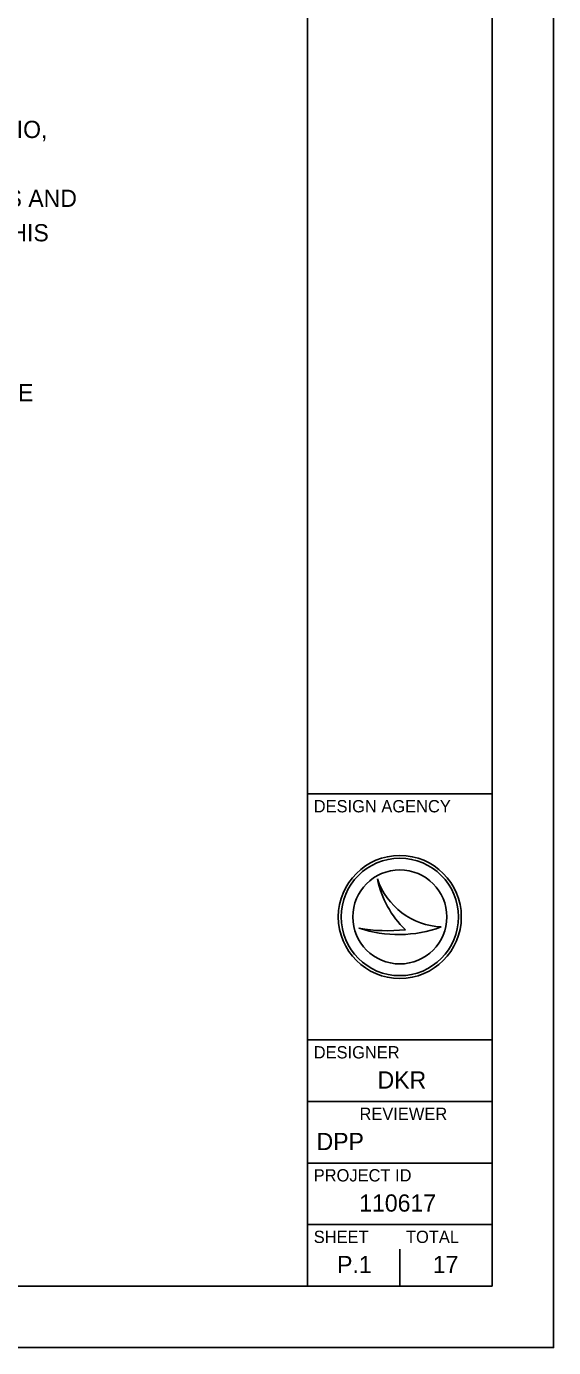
# Model space of a CAD drawing. Extents: x 0 to 34, y 0 to 22.
# Drawn here: x 29.71 to 34, y 0 to 10.74 of the extents above; entities that cross this region are included whole.
import ezdxf

# ---------------------------------------------------------------- set-up
doc = ezdxf.new("R2010")
doc.units = 0
for name, color, linetype in [('SH_Border', 7, 'Continuous'), ('SH_Cut_Line', 7, 'Continuous'), ('SH_Data', 7, 'Continuous')]:
    doc.layers.add(name, color=color, linetype=linetype)

msp = doc.modelspace()

# ---------------------------------------------------------------- linework, layer by layer
at = {"layer": 'SH_Border'}
msp.add_lwpolyline([(0, 0), (34, 0), (34, 22), (0, 22)], close=True, dxfattribs=at)
at = {"layer": 'SH_Cut_Line'}
for p, q in [((32.567, 3.81), (32.567, 3.81)), ((32.75, 3.5), (32.75, 3.5)), ((32.417, 3.41), (32.417, 3.41)), ((33.087, 3.419), (33.087, 3.419)), ((32.75, 0.5), (32.75, 0.8)), ((32.375, 0.675), (32.375, 0.675))]:
    msp.add_line(p, q, dxfattribs=at)
for radius in [0.5, 0.477, 0.477, 0.382]:
    msp.add_circle((32.75, 3.5), radius, dxfattribs=at)
for centre, radius, start, end in [((33.116, 3.998), 0.58, 198.9257, 198.9319), ((33.347, 3.97), 0.796, 191.6379, 191.6421), ((33.116, 3.998), 0.58, 198.9319, 267.1657), ((33.347, 3.97), 0.796, 191.6421, 226.0947), ((32.739, 4.37), 1.013, 251.4576, 290.0832), ((32.648, 4.654), 1.266, 259.4964, 259.4995), ((32.739, 4.37), 1.013, 251.4527, 251.4576), ((32.648, 4.654), 1.266, 259.4995, 276.6672)]:
    msp.add_arc(centre, radius, start, end, dxfattribs=at)
at = {"layer": 'SH_Data'}
for p, q in [((32, 0.5), (32, 21.5)), ((32, 4.5), (33.5, 4.5)), ((32, 2.5), (33.5, 2.5)), ((32, 2), (33.5, 2)), ((32, 1.5), (33.5, 1.5)), ((32, 1), (33.5, 1))]:
    msp.add_line(p, q, dxfattribs=at)
msp.add_lwpolyline([(1.5, 21.5), (33.5, 21.5), (33.5, 0.5), (1.5, 0.5)], close=True, dxfattribs=at)

# ---------------------------------------------------------------- texts
at = {"layer": 'SH_Cut_Line'}
for s, height, p in [('THE STANDARD SPECIFICATIONS OF THE STATE OF OHIO, ', 0.14, (24.528, 9.831)), ('SUPPLEMENTAL SPECIFICATIONS LISTED IN THE PLANS AND ', 0.14, (24.528, 9.271)), ('CHANGES LISTED IN THE PROPOSAL SHALL GOVERN THIS ', 0.14, (24.528, 8.991)), ('THE MAKING OF THIS IMPROVEMENT WILL NOT REQUIRE', 0.14, (24.528, 7.692)), ('DESIGN AGENCY', 0.1, (32.05, 4.35)), ('DESIGNER', 0.1, (32.05, 2.35)), ('DKR', 0.14, (32.569, 2.105)), ('REVIEWER', 0.1, (32.422, 1.85)), ('DPP', 0.14, (32.073, 1.605)), ('PROJECT ID', 0.1, (32.05, 1.35)), ('110617', 0.14, (32.42, 1.105)), ('SHEET', 0.1, (32.05, 0.85)), ('TOTAL', 0.1, (32.8, 0.85)), ('P.1', 0.14, (32.24, 0.605)), ('17', 0.14, (33.018, 0.605))]:
    msp.add_text(s, height=height, dxfattribs=at).set_placement(p)

doc.saveas('drawing.dxf')
